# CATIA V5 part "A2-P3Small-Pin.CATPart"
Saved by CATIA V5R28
Part number: Small-Pin
Revision: ANY
Definition: UNKNOWN
Nomenclature: Small-Pin
Source: Unknown
Bounding box of the stored display mesh (mm): x -8.5 to 8.5, y -8.5 to 8.5, z -39 to 39
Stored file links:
  E:\TP Catia - Documents\Additional Exercise\Contrôle\Problem-3-Section-J\A2-P3Small-Pin.CATPart
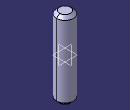
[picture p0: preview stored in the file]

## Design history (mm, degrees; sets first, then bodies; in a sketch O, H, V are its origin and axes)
Body1 "Imported1" (main body)
  Solid1: solid without history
